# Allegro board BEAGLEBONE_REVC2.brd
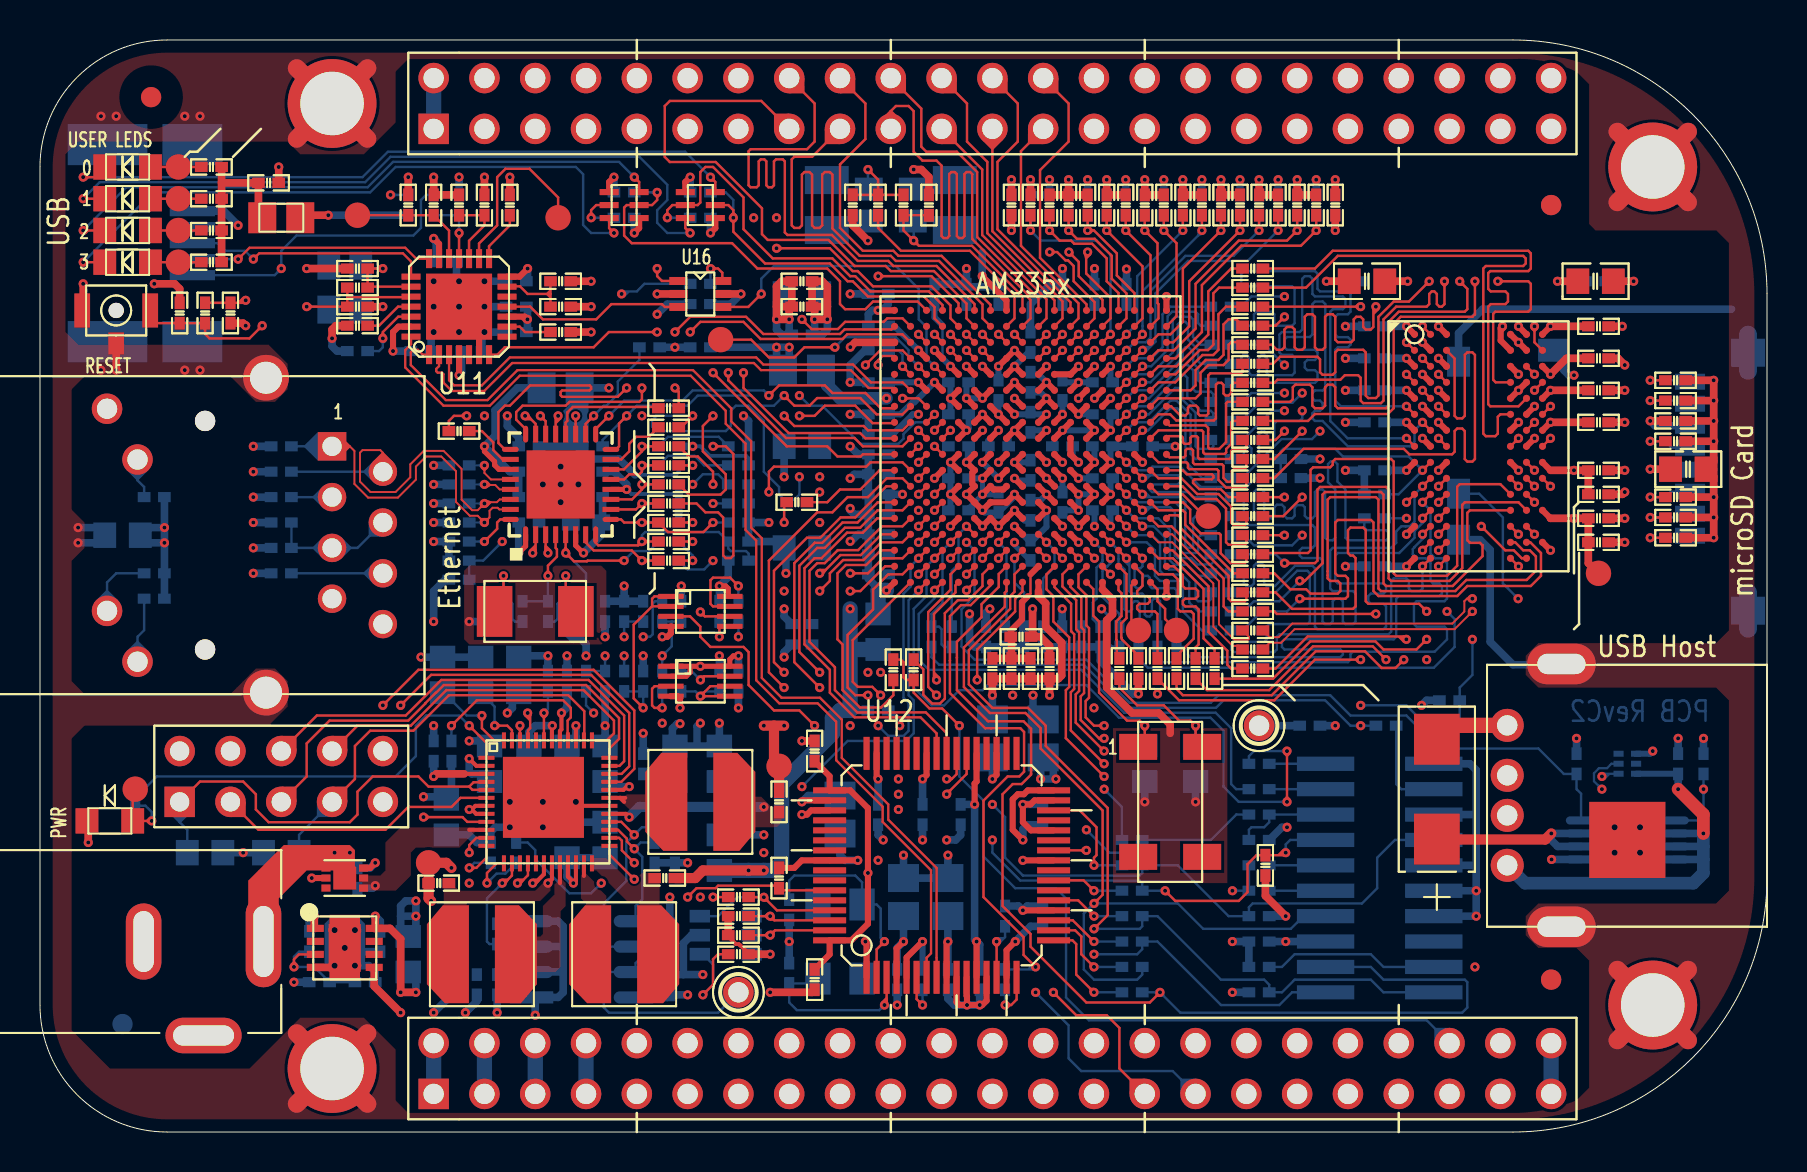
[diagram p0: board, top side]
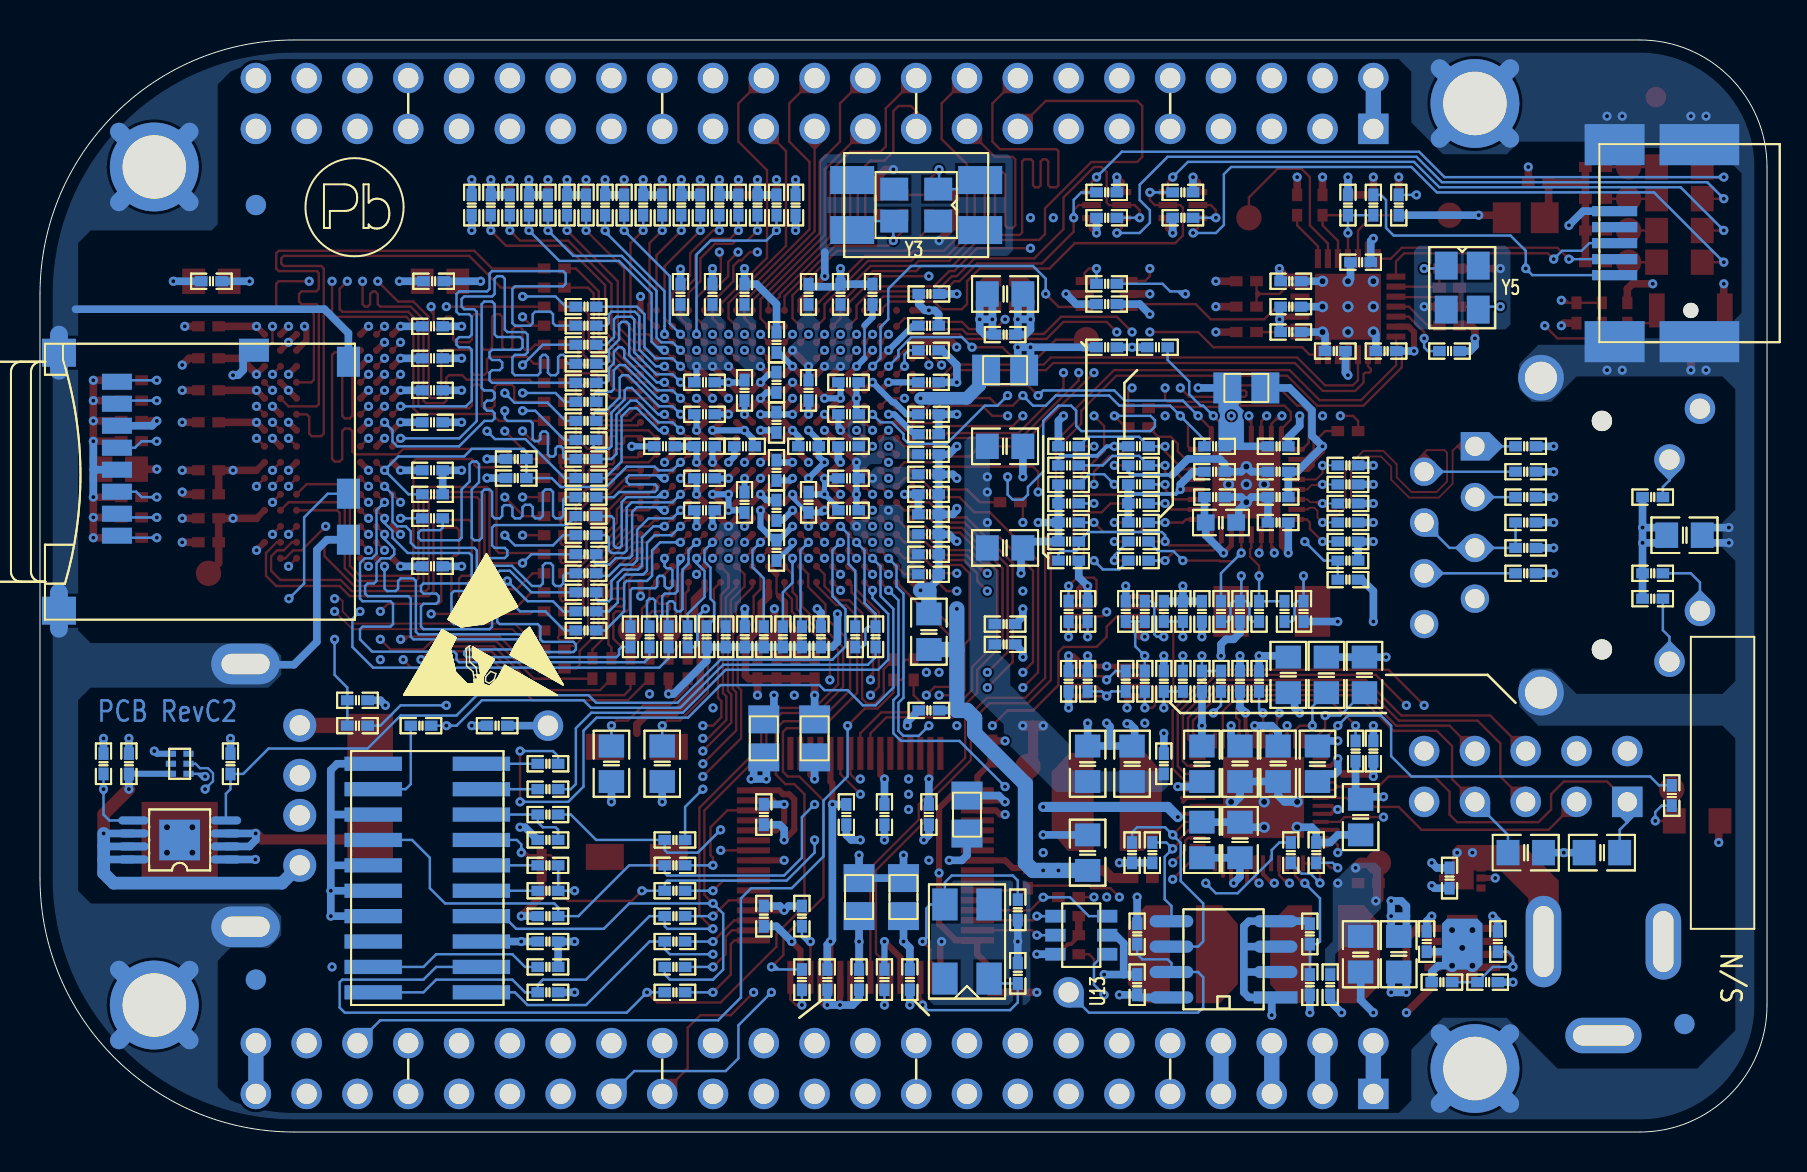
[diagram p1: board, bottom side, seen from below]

Outline 86.36 x 54.61 mm; copper layers: TOP, LYR2_GND, LYR3, LYR4, LYR5_PWR, BOTTOM. Coordinates in mm from the lower left corner of the outline.
Outline path: 0,48.26 0,6.35 arc(1.86,1.86) 6.35,0 73.66,0 arc(82.64,3.72) 86.36,12.7 86.36,41.91 arc(82.64,50.89) 73.66,54.61 6.35,54.61 arc(1.86,52.75) 0,48.26

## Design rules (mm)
net group FT_D: nets FT_DM FT_DP
net group PDDR_CLK: nets PDDR_CLK PDDR_CLKN
net group RX: nets RXN RXP
net group TX: nets TXN TXP
net group USB0: nets USB0_DM USB0_DP
net group USB1: nets USB1_DM USB1_DP
net group USBD: nets USBDM_DN USBDP_UP
net group CLK: nets MMC0_CLKO
net group DDR_ADD: nets DDR_A0 DDR_A1 DDR_A2 DDR_A3 DDR_A4 DDR_A5 DDR_A6 DDR_A7 DDR_A8 DDR_A9 DDR_A10 DDR_A11 DDR_A12 DDR_A13 DDR_BA0 DDR_BA1 DDR_BA2 DDR_CASN DDR_CKE DDR_CLK DDR_CLKN DDR_CSN DDR_ODT DDR_RASN DDR_WEN
net group DDR_DATA: nets DDR_D0 DDR_D1 DDR_D2 DDR_D3 DDR_D4 DDR_D5 DDR_D6 DDR_D7 DDR_D8 DDR_D9 DDR_D10 DDR_D11 DDR_D12 DDR_D13 DDR_D14 DDR_D15 DDR_DQM0 DDR_DQM1 DDR_DQS0 DDR_DQS1 DDR_DQSN0 DDR_DQSN1

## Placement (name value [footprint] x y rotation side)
C1  4.7uF,6.3V  [402]  15.88 12.7 90 bottom
C2  4.7uF,6.3V  [402]  22.54 13.97 90 bottom
C3  10uF,10V  [805]  8.26 13.97 180 bottom
C4  10uF,10V  [805]  20.13 22.86 270 bottom
C5  10uF,10V  [805]  22.03 22.86 270 bottom
C6  4.7uF,6.3V  [402]  17.02 9.53 270 bottom
C7  4.7uF,50V  [805]  12.06 13.97 180 bottom
C8  10uF,10V  [805]  26.35 14.61 270 bottom
C9  10uF,10V  [805]  28.26 14.61 270 bottom
C10  10uF,10V  [805]  28.26 18.41 270 bottom
C14  10uF,10V  [805]  31.75 18.41 270 bottom
C15  10uF,10V  [805]  33.97 13.97 270 bottom
C16  22uF,6.3V  [805]  20.32 8.89 270 bottom
C17  10uF,10V  [805]  24.45 18.41 90 bottom
C18  10uF,10V  [805]  26.35 18.41 90 bottom
C19  10uF,10V  [805]  22.48 18.41 270 bottom
C20  2.2uF,6.3V  [402]  19.68 19.05 90 bottom
C21  0.01uf,16V,DNI  [402]  34.92 22.54 270 bottom
C22  0.01uf,16V,DNI  [402]  33.97 22.54 90 bottom
C23  25pF,50V  [805]  55.24 18.41 90 bottom
C24  25pF,50V  [805]  57.78 18.41 90 bottom
C25  0.01uf,16V  [402]  30.16 26.04 90 bottom
C26  18pF,50V  [402]  44.45 46.35 90 top
C27  18pF,50V  [402]  40.64 46.35 270 top
C28  0.01uf,16V  [402]  49.53 23.18 270 top
C29  0.01uf,16V  [402]  48.58 23.18 270 top
C30  0.001uf,50V  [402]  47.62 23.18 270 top
C31  10uF,10V  [805]  38.1 29.21 0 bottom
C32  10uF,10V  [805]  38.1 34.29 0 bottom
C33  0.01uf,16V  [402]  45.93 37.49 180 bottom
C34  0.01uf,16V  [402]  49.53 37.49 270 bottom
C35  0.01uf,16V  [402]  51.13 37.09 90 bottom
C36  0.01uf,16V  [402]  41.93 34.89 180 bottom
C37  0.01uf,16V  [402]  47.93 34.29 0 bottom
C38  0.01uf,16V  [402]  49.53 35.49 270 bottom
C39  0.01uf,16V  [402]  51.13 34.29 0 bottom
C40  0.01uf,16V  [402]  49.53 33.09 90 bottom
C41  0.01uf,16V  [402]  51.13 31.49 90 bottom
C42  0.01uf,16V  [402]  48.58 46.35 270 bottom
C43  0.01uf,16V  [402]  49.53 39.49 270 bottom
C44  10uF,10V  [805]  41.91 25.02 270 bottom
C45  0.01uf,16V  [402]  47.93 31.49 90 bottom
C46  0.01uf,16V  [402]  41.91 21.08 0 bottom
C47  0.01uf,16V  [402]  45.93 34.29 180 bottom
C48  0.01uf,16V  [402]  41.93 31.89 180 bottom
C49  0.01uf,16V  [402]  41.93 30.89 180 bottom
C50  10uF,10V  [805]  33.97 18.41 270 bottom
C51  0.01uf,16V  [402]  38.1 42.55 180 top
C52  0.01uf,16V  [402]  38.1 41.27 0 top
C53  0.01uf,16V  [402]  38.1 24.38 180 bottom
C54  0.01uf,16V  [402]  38.1 25.4 180 bottom
C55  0.01uf,16V  [402]  30.16 18.41 90 bottom
C56  0.01uf,16V  [402]  46.33 41.89 90 bottom
C57  0.01uf,16V  [402]  47.31 24.77 270 bottom
C58  0.01uf,16V  [402]  45.93 32.69 180 bottom
C59  0.01uf,16V  [402]  64.77 46.35 90 bottom
C60  0.01uf,16V  [402]  45.93 35.89 180 bottom
C61  0.01uf,16V  [402]  38.1 39.88 180 bottom
C62  0.01uf,16V  [402]  45.93 31.09 180 bottom
C63  0.01uf,16V  [402]  41.91 41.91 180 bottom
C64  0.01uf,16V  [402]  49.53 31.09 270 bottom
C65  0.01uf,16V  [402]  53.13 37.49 0 bottom
C66  0.01uf,16V  [402]  54.33 41.89 270 bottom
C67  0.01uf,16V  [402]  48.58 46.35 90 top
C68  0.01uf,16V  [402]  64.77 46.35 90 top
C69  10uF,10V  [805]  38.1 41.91 180 bottom
C70  0.01uf,16V  [402]  52.73 41.89 270 bottom
C71  0.01uf,16V  [402]  41.93 33.89 0 bottom
C72  0.01uf,16V  [402]  33.02 39.24 180 bottom
C73  0.01uf,16V  [402]  41.93 32.89 180 bottom
C74  0.01uf,16V  [402]  44.73 41.89 90 bottom
C75  0.01uf,16V  [402]  51.13 41.89 90 bottom
C76  0.01uf,16V  [402]  41.93 29.89 180 bottom
C77  0.01uf,16V  [402]  41.93 28.89 180 bottom
C78  0.01uf,16V  [402]  41.93 37.49 180 bottom
C79  0.01uf,16V  [402]  41.93 27.89 180 bottom
C80  0.01uf,16V  [402]  41.93 40.32 180 bottom
C81  0.01uf,16V  [402]  41.93 35.89 180 bottom
C82  0.01uf,16V  [402]  49.53 29.09 270 bottom
C83  1uF,10V  [402]  50.16 24.77 270 bottom
C84  1uF,10V  [402]  48.26 24.77 270 bottom
C85  1uF,10V  [402]  49.21 24.77 270 bottom
C86  0.01uf,16V  [402]  52.07 24.77 270 bottom
C87  0.01uf,16V  [402]  50.48 23.18 270 top
C88  0.01uf,16V  [402]  47.93 37.09 270 bottom
C89  10uF,10V  [805]  77.79 42.55 180 top
C90  0.01uf,16V  [402]  53.13 35.89 180 bottom
C91  0.01uf,16V  [402]  53.13 34.29 180 bottom
C92  0.01uf,16V  [402]  53.13 32.69 180 bottom
C93  0.01uf,16V  [402]  53.13 31.09 180 bottom
C94  0.01uf,16V  [402]  77.79 42.55 0 bottom
C95  0.01uf,16V  [402]  66.67 42.55 180 bottom
C96  0.01uf,16V  [402]  55.13 34.29 0 bottom
C97  1uF,10V  [402]  53.02 24.77 270 bottom
C98  0.01uf,16V  [402]  51.12 24.77 270 bottom
C99  0.01uf,16V  [402]  47.93 41.89 90 bottom
C100  4.7uF,6.3V  [402]  11.43 47.47 0 top
C101  1uF,10V,DNI  [402]  6.99 40.96 90 top
C102  0.1uf,16V  [402]  31.5 7.37 90 bottom
C103  0.01uf,16V  [402]  66.73 40.29 180 bottom
C104  0.01uf,16V  [402]  66.73 38.69 180 bottom
C105  0.01uf,16V  [402]  66.73 37.09 180 bottom
C106  0.01uf,16V  [402]  66.73 35.49 180 bottom
C107  0.01uf,16V  [402]  66.73 33.09 180 bottom
C108  0.01uf,16V  [402]  66.73 28.29 180 bottom
C109  0.01uf,16V  [402]  77.93 40.29 0 top
C110  0.01uf,16V  [402]  77.93 38.69 0 top
C111  0.01uf,16V  [402]  77.93 37.09 0 top
C112  0.01uf,16V  [402]  77.93 35.49 0 top
C113  0.01uf,16V  [402]  77.93 33.09 0 top
C114  0.01uf,16V  [402]  77.93 31.89 0 top
C115  0.01uf,16V  [402]  77.93 30.69 0 top
C116  22uF,6.3V  [805]  66.36 42.55 180 top
C117  0.01uf,16V  [402]  77.93 29.49 0 top
C118  0.01uf,16V  [402]  66.73 31.89 180 bottom
C119  0.1uf,16V  [402]  24.45 30.48 0 bottom
C120  0.1uf,16V  [402]  24.45 31.75 0 bottom
C121  4.7uF,6.3V  [402]  24.45 33.02 0 bottom
C122  0.1uf,16V  [402]  24.45 34.29 180 bottom
C123  0.1uf,16V  [402]  27.62 33.02 180 bottom
C124  470pF  [0603]  27.3 30.48 180 bottom
C125  1uF,10V  [402]  27.62 31.75 180 bottom
C126  15pF,DNI  [402]  12.06 34.29 180 bottom
C127  15pF,DNI  [402]  12.06 33.02 180 bottom
C128  15pF,DNI  [402]  12.06 31.75 180 bottom
C129  15pF,DNI  [402]  12.06 27.94 180 bottom
C130  0.022uF,10V  [402]  12.06 30.48 180 bottom
C131  30pF,50V  [402]  23.18 26.04 270 bottom
C132  30pF,50V  [402]  26.35 26.04 270 bottom
C133  100uF,6.3V  [6032]  69.85 17.14 90 top
C134  0.01uf,16V  [402]  81.92 18.41 90 bottom
C135  10uF,10V  [805]  23.94 22.86 90 bottom
C136  0.1uf,16V  [402]  20.95 46.35 90 top
C137  18pF,50V  [402]  15.88 41.27 180 top
C138  0.1uf,16V  [402]  23.81 42.55 180 bottom
C139  4.7uF,6.3V  [402]  23.81 40.01 180 bottom
C140  0.1uf,16V  [402]  23.81 41.27 180 bottom
C141  0.1uf,16V  [402]  21.59 39.05 0 bottom
C142  0.1uf,16V  [402]  20.32 43.5 0 bottom
C143  0.1uf,16V  [402]  19.05 39.05 0 bottom
C144  18pF,50V  [402]  15.88 43.18 0 top
C145  0.1uf,16V,DNI  [402]  15.88 40.32 180 top
C146  0.1uf,16V,DNI  [402]  26.04 40.01 0 top
C147  0.1uf,16V  [402]  50.16 15.88 270 bottom
C148  0.1uf,16V  [402]  44.13 15.88 270 bottom
C149  0.1uf,16V  [402]  33.02 41.4 0 bottom
C150  0.1uf,16V  [402]  41.91 15.88 90 bottom
C151  0.1uf,16V  [402]  50.16 10.79 270 bottom
C152  4.7uF,6.3V  [402]  46.04 15.88 270 bottom
C153  27pF,50V  [402]  37.47 11.11 90 bottom
C154  0.01uf,16V  [402]  60.96 9.53 180 bottom
C155  27pF,50V  [402]  37.47 7.94 270 bottom
C156  0.1uf,16V  [402]  60.96 14.61 0 bottom
C157  0.1uf,16V  [402]  28.26 26.04 270 bottom
C158  0.1uf,16V  [402]  42.86 7.62 270 bottom
C159  10uF,10V  [805]  82.42 33.15 180 top
C160  0.1uf,16V  [402]  81.79 35.56 180 top
C161  0.1uf,16V  [402]  45.4 7.62 270 bottom
C162  0.1uf,16V  [402]  38.73 19.05 270 top
C163  0.1uf,16V  [402]  38.73 7.62 90 top
C164  0.1uf,16V  [402]  46.99 7.62 90 bottom
C165  10uF,10V  [805]  20.32 15.75 90 bottom
C166  0.1uf,16V  [402]  13.46 9.53 90 bottom
D1  598-8170-107F  [LED0805-1]  3.49 15.56 0 top
D2  598-8170-107F  [LED0805-1]  4.38 48.26 0 top
D3  598-8170-107F  [LED0805-1]  4.38 46.67 0 top
D4  598-8170-107F  [LED0805-1]  4.38 45.09 0 top
D5  598-8170-107F  [LED0805-1]  4.38 43.5 0 top
FB1  150OHM800mA  [SM-7351-IND-0805]  38.1 38.1 0 bottom
FB2  150OHM800mA  [SM-7351-IND-0805]  50.16 19.68 270 bottom
FB3  150OHM800mA  [SM-7351-IND-0805]  47.62 19.68 270 bottom
FB4  150OHM800mA  [SM-7351-IND-0805]  12.06 45.72 0 top
FB5  150OHM800mA  [SM-7351-IND-0805]  26.04 37.21 180 bottom
FB6  150OHM800mA  [SM-7351-IND-0805]  45.4 11.75 270 bottom
FB7  150OHM800mA  [SM-7351-IND-0805]  43.18 11.75 270 bottom
FB8  150OHM800mA  [SM-7351-IND-0805]  40.01 15.88 90 bottom
L1  2.2uH,2.6A  [VLCF5020T]  22.1 8.89 180 top
L2  2.2uH,2.6A  [VLCF5020T]  29.21 8.89 0 top
L3  2.2uH,2.6A  [VLCF5020T]  33.02 16.51 0 top
MTG1  MHOLE  [MTGH200C125D_PL]  14.61 3.17 90 top
MTG2  MHOLE  [MTGH200C125D_PL]  80.64 6.35 90 top
MTG3  MHOLE  [MTGH200C125D_PL]  14.61 51.44 90 top
MTG4  MHOLE  [MTGH200C125D_PL]  80.64 48.26 90 top
NOREF  -  [unnamed]  5.56 51.75 270 top
NOREF#2  -  [#2]  0 0 0 top
NOREF#3  -  [#2]  85.72 39.05 0 top
NOREF#4  -  [#2]  85.72 28.57 0 top
NOREF#5  -  [#2]  6.35 54.61 0 top
NOREF#6  -  [#2]  -11.96 0 90 top
NOREF#7  -  [#2]  80.64 6.35 0 top
NOREF#8  -  [#2]  80.64 48.26 0 top
NOREF#9  -  [#2]  80.64 6.35 0 top
NOREF#10  -  [#2]  14.61 51.44 0 top
NOREF#11  -  [unnamed]  75.56 46.35 270 top
NOREF#12  -  [#2]  14.61 3.17 0 top
NOREF#13  -  [#2]  86.36 12.7 0 top
NOREF#14  -  [#2]  14.61 3.17 0 top
NOREF#15  -  [#2]  81.92 52.07 0 top
NOREF#16  -  [unnamed]  75.56 7.62 270 top
NOREF#17  -  [#2]  0 -11.96 0 top
NOREF#18  -  [#2]  -368.3 -256.54 0 top
NOREF#19  -  [#2]  86.36 39.69 0 top
NOREF#20  -  [#2]  85.72 28.57 0 top
NOREF#21  -  [#2]  0 0 0 top
NOREF#22  -  [#2]  -368.17 -256.47 0 top
NOREF#23  -  [#2]  86.36 27.94 0 top
NOREF#24  -  [#2]  1.91 53.34 180 bottom
NOREF#25  -  [unnamed]  75.56 7.62 270 bottom
NOREF#26  -  [unnamed]  4.13 5.4 270 bottom
NOREF#27  -  [unnamed]  75.56 46.35 270 bottom
P2  USB-A Conn. - 87520-xx1xx  [USB_A_SH]  73.37 13.34 90 top
P3  mini USB-B  [USB-MINI-SMT-NUM]  7.62 44.45 90 bottom
P4  MOLEX 502570-001  [CON8SMD-MICRO_SD_14P3X15P9]  70.61 33.02 90 bottom
P5  PJ-200A  [CONN3-PWR-PJ102A]  11.18 9.53 180 top
P6  HDR5x2  [HEADER10X2]  6.99 16.51 90 top
P7  CTI JTAG,DNI  [HEADER10X2_SMD]  66.99 12.7 90 bottom
P8  FEMALE HEADER 2x23  [HEADER23X2]  19.68 50.16 0 top
P9  FEMALE HEADER 2x23  [HEADER23X2]  19.68 1.91 0 top
P10  WE_7499010211A  [RJ45-7499010211A]  14.61 34.29 270 top
Q1  DMC56404  [SMINI6-F3-B]  33.02 46.35 90 top
Q2  DMC56404  [SMINI6-F3-B]  29.21 46.35 90 top
R1  4.75K,1%  [402]  22.86 9.91 270 bottom
R2  12.1K,1%  [402]  22.86 7.37 270 bottom
R3  .1,0805  [805]  18.41 8.89 90 bottom
R4  1.5K,5%  [402]  30.73 13.97 90 bottom
R5  10K,1%,DNI  [402]  34.92 31.43 0 bottom
R6  470,5%  [402]  4.76 16.83 270 bottom
R7  1.5K,5%  [402]  31.75 13.97 90 bottom
R8  100K,1%  [402]  27.3 22.54 270 bottom
R9  100K,1%  [402]  28.26 22.54 90 bottom
R10  0,DNI  [402]  29.21 22.54 90 bottom
R11  0,1%  [402]  23.81 13.97 90 bottom
R12  0,1%  [402]  19.94 12.45 180 top
R13  0,1%  [402]  36.96 16.51 90 top
R14  0,1%  [402]  21.84 7.37 270 bottom
R15  0,1%  [402]  26.35 22.54 90 bottom
R16  470,5%  [402]  5.71 27.94 180 bottom
R17  1.1K,1%,DNI  [402]  32.07 22.54 270 bottom
R18  12.1K,1%  [402]  32.07 26.04 90 bottom
R19  0,1%  [402]  20.57 19.05 270 bottom
R20  100K,1%  [402]  29.21 26.04 90 bottom
R21  1M,1%  [402]  43.18 46.35 90 top
R22  0,1%  [402]  53.98 23.18 90 top
R23  10K,1%  [402]  9.53 40.96 90 top
R24  0,1%  [402]  41.91 46.35 270 top
R25  33,0402  [402]  60.64 31.75 180 top
R26  33,0402  [402]  56.83 24.77 90 bottom
R27  0,1%  [402]  8.26 40.96 270 top
R28  0,1%  [402]  34.92 26.04 270 bottom
R29  33,0402  [402]  59.05 28.89 180 bottom
R30  33,0402  [402]  59.05 26.04 180 bottom
R31  33,0402  [402]  58.74 23.18 90 top
R32  33,0402  [402]  57.78 23.18 90 top
R33  33,0402  [402]  54.93 24.77 90 bottom
R34  33,0402  [402]  60.64 26.04 180 top
R35  33,0402  [402]  59.05 25.08 180 bottom
R36  33,0402  [402]  60.64 23.18 180 top
R37  33,0402  [402]  59.05 27.94 180 bottom
R38  33,0402  [402]  60.64 27.94 180 top
R39  33,0402  [402]  59.05 26.99 180 bottom
R40  33,0402  [402]  59.05 31.75 180 bottom
R41  33,0402  [402]  55.88 24.77 90 bottom
R42  33,0402  [402]  60.64 26.99 180 top
R43  33,0402  [402]  55.88 23.18 90 top
R44  33,0402  [402]  59.05 36.51 180 bottom
R45  33,0402  [402]  59.05 37.47 180 bottom
R46  33,0402  [402]  60.64 40.32 180 top
R47  33,0402  [402]  60.64 41.27 180 top
R48  33,0402  [402]  59.05 38.42 180 bottom
R49  33,0402  [402]  59.05 39.37 180 bottom
R50  33,0402  [402]  59.05 40.32 180 bottom
R51  33,0402  [402]  59.05 41.27 180 bottom
R52  33,0402  [402]  60.64 33.66 180 top
R53  33,0402  [402]  60.64 34.61 180 top
R54  33,0402  [402]  60.64 35.56 180 top
R55  33,0402  [402]  59.05 32.7 180 bottom
R56  33,0402  [402]  59.05 33.66 180 bottom
R57  33,0402  [402]  59.05 34.61 180 bottom
R58  33,0402  [402]  59.05 35.56 180 bottom
R59  33,0402  [402]  60.64 38.42 180 top
R60  33,0402  [402]  60.64 24.13 180 top
R61  33,0402  [402]  60.64 25.08 180 top
R62  33,0402  [402]  59.05 30.8 180 bottom
R63  33,0402  [402]  60.64 30.8 180 top
R64  33,0402  [402]  60.64 28.89 180 top
R65  33,0402  [402]  59.05 29.84 180 bottom
R66  33,0402  [402]  56.83 23.18 90 top
R67  33,0402  [402]  60.64 39.37 180 top
R68  33,0402  [402]  60.64 42.23 180 top
R69  33,0402  [402]  60.64 43.18 180 top
R70  33,0402  [402]  60.64 32.7 180 top
R71  33,0402  [402]  60.64 36.51 180 top
R72  33,0402  [402]  60.64 37.47 180 top
R73  33,0402  [402]  60.64 29.84 180 top
R74  2.2K,1%  [402]  62.55 32.7 180 bottom
R75  2.2K,1%  [402]  62.55 33.66 0 bottom
R76  49.9,1%  [402]  63.5 20.32 0 bottom
R77  4.75K,1%  [402]  53.98 24.77 90 bottom
R78  0,1%  [402]  49.05 24.77 180 top
R79  10K,1%  [402]  54.93 23.18 90 top
R80  100K,1%  [402]  63.82 46.35 270 top
R81  100K,1%  [402]  62.87 46.35 270 top
R82  100K,1%  [402]  61.91 46.35 270 top
R83  100K,1%,DNI  [402]  60.96 46.35 270 top
R84  100K,1%  [402]  60.01 46.35 270 top
R85  100K,1%,DNI  [402]  59.05 46.35 270 top
R86  100K,1%,DNI  [402]  58.1 46.35 270 top
R87  100K,1%,DNI  [402]  57.15 46.35 270 top
R88  100K,1%,DNI  [402]  56.2 46.35 270 top
R89  100K,1%,DNI  [402]  55.24 46.35 270 top
R90  100K,1%,DNI  [402]  53.34 46.35 270 top
R91  100K,1%,DNI  [402]  51.44 46.35 270 top
R92  100K,1%,DNI  [402]  54.29 46.35 270 top
R93  100K,1%,DNI  [402]  52.39 46.35 270 top
R94  100K,1%  [402]  50.48 46.35 270 top
R95  100K,1%,DNI  [402]  49.53 46.35 270 top
R96  470,5%  [402]  8.57 48.26 180 top
R97  470,5%  [402]  8.57 46.67 180 top
R98  470,5%  [402]  8.57 45.09 180 top
R99  470,5%  [402]  8.57 43.5 180 top
R100  42.2K,1%,DNI  [402]  63.82 46.35 90 bottom
R101  42.2K,1%,DNI  [402]  62.87 46.35 90 bottom
R102  42.2K,1%,DNI  [402]  61.91 46.35 90 bottom
R103  42.2K,1%  [402]  60.96 46.35 90 bottom
R104  42.2K,1%,DNI  [402]  60.01 46.35 90 bottom
R105  42.2K,1%  [402]  59.05 46.35 90 bottom
R106  42.2K,1%  [402]  58.1 46.35 90 bottom
R107  42.2K,1%  [402]  57.15 46.35 90 bottom
R108  42.2K,1%  [402]  56.2 46.35 90 bottom
R109  42.2K,1%  [402]  55.24 46.35 90 bottom
R110  42.2K,1%  [402]  53.34 46.35 90 bottom
R111  42.2K,1%  [402]  51.44 46.35 90 bottom
R112  42.2K,1%  [402]  54.29 46.35 90 bottom
R113  42.2K,1%  [402]  52.39 46.35 90 bottom
R114  42.2K,1%,DNI  [402]  50.48 46.35 90 bottom
R115  42.2K,1%  [402]  49.53 46.35 90 bottom
R116  100K,1%  [402]  33.02 45.72 0 bottom
R117  100K,1%  [402]  33.02 46.99 180 bottom
R118  100K,1%  [402]  29.21 45.72 0 bottom
R119  100K,1%  [402]  29.21 46.99 180 bottom
R120  0,1%  [402]  66.73 30.69 0 bottom
R121  0,1%  [402]  25.4 22.54 90 bottom
R122  10K,1%  [402]  31.43 34.29 0 bottom
R123  10K,1%  [402]  31.43 31.43 0 bottom
R124  10K,1%  [402]  31.43 32.38 0 bottom
R125  10K,1%  [402]  31.43 33.34 0 bottom
R126  10K,1%,DNI  [402]  34.92 33.34 180 bottom
R127  10K,1%,DNI  [402]  34.92 34.29 0 bottom
R128  470,5%  [402]  5.71 31.75 180 bottom
R129  49.9,1%  [402]  20.95 30.48 180 bottom
R130  49.9,1%  [402]  20.95 31.43 180 bottom
R131  1.5K,5%  [402]  27.62 34.29 0 bottom
R132  100,1%  [402]  31.43 31.43 180 top
R133  49.9,1%  [402]  20.95 32.38 180 bottom
R134  49.9,1%  [402]  20.95 33.34 180 bottom
R135  100,1%  [402]  31.43 32.38 180 top
R136  100,1%  [402]  31.43 28.57 180 bottom
R137  100,1%  [402]  31.43 33.34 180 top
R138  .1,0805  [805]  4.13 29.84 180 bottom
R139  100,1%  [402]  31.43 34.29 180 top
R140  1M,1%,DNI  [402]  25.4 26.04 270 bottom
R141  10K,1%  [402]  31.11 26.04 90 bottom
R142  0,1%  [402]  12.06 29.21 180 bottom
R143  0,1%,DNI  [402]  31.11 22.54 90 bottom
R144  10,1%  [402]  24.13 26.04 270 bottom
R145  12.1K,1%  [402]  20.95 29.53 180 bottom
R146  0,1%  [402]  41.93 39.09 180 bottom
R147  10K,1%  [402]  76.83 18.41 90 bottom
R148  10K,1%  [402]  83.19 18.41 270 bottom
R149  100K,1%  [402]  19.68 46.35 270 bottom
R150  52.3K,1%  [402]  13.97 7.49 180 bottom
R151  100K,1%  [402]  20.95 46.35 90 bottom
R152  4.75K,1%  [402]  18.41 46.35 90 bottom
R153  100,1%  [402]  31.43 30.48 180 top
R154  10K,1%,DNI  [402]  26.04 41.27 180 top
R155  10K,1%,DNI  [402]  18.41 46.35 270 top
R156  100K,1%  [402]  22.23 46.35 270 top
R157  12.1K,1%  [402]  15.88 39.05 180 bottom
R158  10K,1%  [402]  26.04 42.55 0 top
R159  100K,1%  [402]  19.68 46.35 90 top
R160  1M,1%,DNI  [402]  15.88 42.23 0 top
R161  0,1%  [402]  23.5 46.35 270 top
R162  4.75K,1%  [402]  33.97 26.04 270 bottom
R163  0,1%  [402]  33.02 42.42 180 bottom
R164  0,1%  [402]  48.26 7.62 90 bottom
R165  0,1%  [402]  54.61 6.99 0 bottom
R166  0,1%  [402]  54.61 8.26 0 bottom
R167  12.1K,1%  [402]  44.13 7.62 270 bottom
R168  0,1%  [402]  54.61 9.53 0 bottom
R169  0,1%  [402]  54.61 10.79 0 bottom
R170  0,1%  [402]  54.61 12.06 0 bottom
R171  0,1%  [402]  54.61 13.34 0 bottom
R172  0,1%  [402]  54.61 14.61 0 bottom
R173  10K,1%  [402]  34.92 9.84 0 top
R174  10K,1%  [402]  34.92 10.79 0 top
R175  2.2K,1%  [402]  48.26 10.79 270 bottom
R176  4.75K,1%  [402]  61.28 13.34 90 top
R177  0,DNI  [402]  60.96 8.26 180 bottom
R178  0,DNI  [402]  60.96 12.06 0 bottom
R179  4.75K,1%  [402]  60.96 10.79 180 bottom
R180  0,DNI  [402]  60.96 13.34 0 bottom
R181  10K,1%,DNI  [402]  36.96 12.7 270 top
R182  100,1%,DNI  [402]  60.96 15.88 0 bottom
R183  0,DNI  [402]  60.96 17.14 0 bottom
R184  0,DNI  [402]  67.31 20.32 180 bottom
R185  0,DNI  [402]  60.96 18.41 0 bottom
R186  4.75K,1%  [402]  60.96 6.99 180 bottom
R187  10K,1%  [402]  34.92 8.89 180 top
R188  2.2K,1%  [402]  34.92 11.75 0 top
R189  30.1K,1%  [402]  16.26 7.49 0 bottom
R190  10K,1%  [402]  81.79 29.72 180 top
R191  10K,1%  [402]  81.79 31.75 180 top
R192  10K,1%  [402]  81.79 34.54 180 top
R193  10K,1%  [402]  81.79 36.58 180 top
R194  10K,1%  [402]  81.79 37.59 180 top
R195  10K,1%  [402]  81.79 30.73 180 top
R196  10K,1%  [402]  70.48 21.59 180 bottom
R197  0,1%  [402]  70.48 20.32 180 bottom
R198  10K,1%,DNI  [402]  34.92 32.38 0 bottom
R199  0,1%  [402]  27.3 26.04 90 bottom
R200  0,1%,DNI  [402]  31.43 29.53 180 bottom
R201  33,0402  [402]  37.85 31.5 180 top
R202  0,1%  [402]  43.69 23.11 90 top
R203  100K,1%  [402]  30.16 22.54 270 bottom
R204  0,1%  [402]  31.24 12.7 0 top
R205  100,1%  [402]  31.43 29.53 180 top
R206  100,1%  [402]  31.43 36.2 180 top
R207  100,1%  [402]  31.43 35.24 180 top
R208  100,1%  [402]  20.95 35.05 0 top
R209  10,1%,DNI  [402]  31.43 28.57 180 top
R210  10K,1%  [402]  31.5 9.91 270 bottom
R211  10K,1%,DNI  [402]  31.43 30.48 0 bottom
R212  10K,1%  [402]  34.92 30.48 0 bottom
R213  10K,1%,DNI  [402]  34.92 28.57 180 bottom
R214  10K,1%  [402]  34.92 29.53 0 bottom
R215  10K,1%,DNI  [402]  20.95 27.62 180 bottom
R216  10K,1%  [402]  20.95 28.57 180 bottom
R217  0,1%  [402]  42.67 23.11 270 top
R218  0,1%  [402]  44.58 24.77 270 bottom
R219  10K,1%  [402]  5.71 26.67 0 bottom
R220  10K,1%  [402]  30.48 39.24 0 bottom
R221  0,1%  [402]  45.59 24.77 90 bottom
S1  B3U-1100  [SW3_4X2P5]  3.81 41.08 0 top
TP1  TESTPT1  [TP1-8040]  60.96 20.32 0 top
TP2  TESTPT1  [TP1-8040]  34.92 6.99 0 top
TP3  TESTPT1  [TP60C_SMD]  58.42 30.8 0 top
TP4  TESTPT1  [TP60C_SMD]  34.04 39.62 0 top
TP5  TESTPT1  [TP60C_SMD]  56.83 25.08 0 top
TP6  TESTPT1  [TP60C_SMD]  54.93 25.08 0 top
TP7  TESTPT1  [TP60C_SMD]  15.88 45.85 0 top
TP8  TESTPT1  [TP60C_SMD]  25.91 45.72 0 top
TP10  TESTPT1  [TP60C_SMD]  6.92 48.26 0 top
TP11  TESTPT1  [TP60C_SMD]  6.92 46.67 0 top
TP12  TESTPT1  [TP60C_SMD]  6.92 45.09 0 top
TP13  TESTPT1  [TP60C_SMD]  6.92 43.5 0 top
TP14  TESTPT1  [TP60C_SMD]  4.76 17.14 0 top
TP15  TESTPT1  [TP60C_SMD]  19.43 13.46 0 top
TP17  TESTPT1  [TP60C_SMD]  36.96 18.29 0 top
TP18  TESTPT1  [TP60C_SMD]  77.93 27.94 0 top
U1  NCP349  [DFN6-1P6X2]  15.24 12.7 270 top
U2  TPS65217b  [U_48_RSL]  25.4 16.51 0 top
U5  AM335X_ZCZ  [AM33XX_15X15]  49.53 34.29 180 top
U6  MT47H128M16RT-25E:C  [BGA84_8X12P5_P8MM]  71.93 34.29 0 top
U7  CAT24C256W  [SOIC_8]  27.18 8.64 90 bottom
U8  TPS73701DRBR  [DRB8-14X33-PAD]  15.24 9.21 270 top
U9  TPS2051 (DGN)  [DGN-16X60]  79.38 14.61 90 bottom
U10  TPD4S012  [U_6_DRY]  79.38 18.41 90 bottom
U11  USB2412_QFN28_MKTG  [QFN28_5X5]  20.95 41.27 90 top
U12  FT2232LQFN64  [LQFP64_10X10]  45.09 13.34 90 top
U13  93LC56B_SOT23-6  [SOT23-6]  34.29 9.84 90 bottom
U14  SN74LVC2G00DCU  [U_8_DCU]  33.02 26.04 270 top
U15  LAN8710A  [QFN32_5X5MM_EP3P3MM]  26.04 32.38 0 top
U16  SN74LVC2G07DCK  [DCK6_2P15X1P4]  33.02 41.91 270 top
U17  SN74AUP2G08,DNI  [U_8_DCU]  33.02 22.54 270 top
Y1  32.768KHz MC-306  [MC-306]  56.52 16.51 270 top
Y2  24MHz,DNI  [SM_CRY_SCC18]  42.55 46.35 270 bottom
Y3  24MHz  [XTAL4_3P2X2P5_SMD]  42.55 46.35 0 bottom
Y4  25.000MHz  [XTAL2_5X3P2_SMD]  24.77 26.04 180 top
Y5  24MHz  [XTAL4_3P2X2P5_SMD]  15.24 42.23 270 bottom
Y6  12.000MHz  [XTAL4_3P2X5SMD]  40.01 9.53 90 bottom

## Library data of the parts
C1 C2 C6 C100 C121 C139 C152 = CAP_4.7uF_X5R_6.3V_10%_0603
C3-C5 C8-C10 C14 C15 C17-C19 C31 C32 C44 C50 C69 C89 C135 C159 C165 = CAP_10uF_Y5V_10V_10%_0805
C7 = CAP_4.7uF_X5R_50V_10%_0805
C16 C116 = CAP_22uF_X5R_6.3V_120%_0805
C20 = CAP_2.2uF_X5R_6.3V_10%_0402
C21 C22 C25 C28 C29 C33-C43 C45-C49 C51-C68 C70-C82 C86-C88 C90-C96 C98 C99 C103-C115 C117 C118 C134 C154 = CAP_0.01uf_X7R_16V_10%_0402
C23 C24 = CAP_25PF_NPO_100V_5%_0805
C26 C27 C137 C144 C153 C155 = CAP_18PF_COG_50V_5%_0402
C30 = CAP_0.001_X7R_50V_5%_0402
C83-C85 C97 C101 C125 = CAP_1.0UF_X5R_10V_10%_0402
C102 C119 C120 C122 C123 C136 C138 C140-C143 C145-C151 C156-C158 C160-C164 C166 = CAP_0.1uF_X7R_16V_10% 0402
C124 = 470pF/5%/50V/C0G/0603_0
C126-C129 = CAP_0402_100pF_COG_50V
C130 = CAP_0402_0.1uf_X5R_10V
C131 C132 = CAP_30PF_COG_50V_5%_0402
C133 = CAP_100UF_TANT_6.3V_3528-21: Tolerance: TOL*; User Part Number: P/N*
D1-D5 = LED_LTST-C150GKT: User Part Number: X; Tolerance: X
FB1-FB8 = FER_180_200_0
L1-L3 = IND_2.2uH_2.6A_10%_SMD
MTG1-MTG4 = MHOLE
P2 = CONN_54819-0578_2: User Part Number: PART#; Tolerance: TOL
P3 = MINI-USB-AB-SOCKET
P4 = microSD_CONN_2
P5 = Power_Jack: Tolerance: X; User Part Number: X
P6 = HDR_10_F_2_0.1
P7 = HDR_10x2_CJTAG
P8 P9 = HDR_46_F_2_0.1_0.1
P10 = CONN_RJ45_MAG_WE_0
Q1 Q2 = RN1907
R1 R2 R23 R79 R142 R144 R147 R148 R154 R155 R158 R173 R174 R181 R187 R190-R196 R219 R220 = RES_10K_1/16W_1%_0402
R3 R138 = RES_0.1_0805
R4 R7 R131 = RES_1.5K_1/16W_5%_0402
R5 R10 R12 R19 R77 R121-R127 R162 R176 R179 R186 R198 R202 R211-R217 = RES_4.75K_1/16W_1%_0402
R6 R16 R96-R99 R128 = RES_470_1/10W_5%_0402
R8 R9 R80-R95 R100-R119 R141 R143 R146 R149 R151 R152 R156 R159 R203 = RES_100K_1/16W_1%_0402
R11 R14 R15 = RES_0_1/16W_1%_0402: signal model: 33OHMRESISTOR1_16W5_0402_SM_735_33
R13 = RES_4.75K_1/16W_1%_0402: signal model: 33OHMRESISTOR1_16W5_0402_SM_735_33
R17 = RES_1.1K_1/16W_1%_0402: signal model: 33OHMRESISTOR1_16W5_0402_SM_735_33
R18 R20 = RES_100K_1/16W_1%_0402: signal model: 33OHMRESISTOR1_16W5_0402_SM_735_33
R21 = RES_1M_1/16W_1%_0402: signal model: 33OHMRESISTOR1_16W5_0402_SM_735_33
R22 R24 R27 R28 R78 R161 R163-R166 R168-R172 R177 R178 R180 R183-R185 R197 R199 R200 R204 R210 R218 R221 = RES_0_1/16W_1%_0402
R25 R26 R29 R30 R32 R45 R46 R48 R50-R73 R201 = RES_33_0402
R31 R33-R44 R47 R49 = RES_33_0402: signal model: 33OHMRESISTOR1_16W5_0402_SM_735_33
R74 R75 R175 R188 = RES_2.2K_1/16W_1%_0402
R76 R129 R130 R133 R134 = RES_4.7K_0402
R120 = ZeroOhmResistor1/16W0402
R132 R135-R137 R139 R182 = RES_100_1/10W_5%_0402
R140 R160 = RES_1M_1/16W_1%_0402
R145 R157 R167 = RES_12.1K_1/16W_1%_0402
R150 R189 = RES_0: tolerance: 1%
R153 R205-R209 = 100-1/10W-1%-0603_4
S1 = SW_DP_MOM
TP1-TP8 TP10-TP15 TP17 TP18 = TESTPT1
U1 = PWR_NCP349_6-DFN: Tolerance: X; User Part Number: X
U2 = PWR_TPS65217_2
U5 = IC_AM335X_ZCE_1
U6 = MEM_MT47H64M16_FBGA84_1
U7 = CAT24C256W
U8 = TPS73701_0: Tolerance: X; User Part Number: X
U9 = TPS2061_0: User Part Number: X; Tolerance: X
U10 = PROT_TPD4S012
U11 = USB2412_QFN28_MKTG_2
U12 = IC_FT2232H_LQFP64
U13 = IC_93C46B_SSOT23-6
U14 = IC_SN74LVC2G38_8-VSSOP
U15 = LAN8710 QFN32_1
U16 = IC_SN74LVC2G07DCK
U17 = IC_SN74AUP2G08_8-VSSOP
Y1 = CRYS_32_768KHz_SMD32
Y2 Y3 Y5 = CRYS_24MHz_SCC
Y4 = Suntsu ITEMP 25MHz _0.005% 20pf
Y6 = XTAL_12MHZ_HC-49SMT_0: Tolerance: TOL*; User Part Number: P/N*

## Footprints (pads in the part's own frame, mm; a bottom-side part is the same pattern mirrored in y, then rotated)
402
  rect 0.635x0.508 smd: 1(-0.508,0) 2(0.508,0)
0603
  rect 0.889x0.813 smd: 1(-0.762,0) 2(0.762,0)
805
  rect 1.143x1.27 smd: 1(-0.889,0) 2(0.889,0)
6032
  rect 2.54x2.286 smd: 1(-2.499,0) 2(2.499,0)
AM33XX_15X15
  round 0.356 smd: A1(-6.8,6.8) A2(-6,6.8) A3(-5.2,6.8) A4(-4.4,6.8) A5(-3.6,6.8) A6(-2.8,6.8) A7(-2,6.8) A8(-1.2,6.8) A9(-0.4,6.8) A10(0.4,6.8) A11(1.2,6.8) A12(2,6.8) A13(2.8,6.8) A14(3.6,6.8) A15(4.4,6.8) A16(5.2,6.8) A17(6,6.8) A18(6.8,6.8) B1(-6.8,6) B2(-6,6) B3(-5.2,6) B4(-4.4,6) B5(-3.6,6) B6(-2.8,6) B7(-2,6) B8(-1.2,6) B9(-0.4,6) B10(0.4,6) B11(1.2,6) B12(2,6) B13(2.8,6) B14(3.6,6) B15(4.4,6) B16(5.2,6) B17(6,6) B18(6.8,6) C1(-6.8,5.2) C2(-6,5.2) C3(-5.2,5.2) C4(-4.4,5.2) C5(-3.6,5.2) C6(-2.8,5.2) C7(-2,5.2) C8(-1.2,5.2) C9(-0.4,5.2) C10(0.4,5.2) C11(1.2,5.2) C12(2,5.2) C13(2.8,5.2) C14(3.6,5.2) C15(4.4,5.2) C16(5.2,5.2) C17(6,5.2) C18(6.8,5.2) D1(-6.8,4.4) D2(-6,4.4) D3(-5.2,4.4) D4(-4.4,4.4) D5(-3.6,4.4) D6(-2.8,4.4) D7(-2,4.4) D8(-1.2,4.4) D9(-0.4,4.4) D10(0.4,4.4) D11(1.2,4.4) D12(2,4.4) D13(2.8,4.4) D14(3.6,4.4) D15(4.4,4.4) D16(5.2,4.4) D17(6,4.4) D18(6.8,4.4) E1(-6.8,3.6) E2(-6,3.6) E3(-5.2,3.6) E4(-4.4,3.6) E5(-3.6,3.6) E6(-2.8,3.6) E7(-2,3.6) E8(-1.2,3.6) E9(-0.4,3.6) E10(0.4,3.6) E11(1.2,3.6) E12(2,3.6) E13(2.8,3.6) E14(3.6,3.6) E15(4.4,3.6) E16(5.2,3.6) E17(6,3.6) E18(6.8,3.6) F1(-6.8,2.8) F2(-6,2.8) F3(-5.2,2.8) F4(-4.4,2.8) F5(-3.6,2.8) F6(-2.8,2.8) F7(-2,2.8) F8(-1.2,2.8) F9(-0.4,2.8) F10(0.4,2.8) F11(1.2,2.8) F12(2,2.8) F13(2.8,2.8) F14(3.6,2.8) F15(4.4,2.8) F16(5.2,2.8) F17(6,2.8) F18(6.8,2.8) G1(-6.8,2) G2(-6,2) G3(-5.2,2) G4(-4.4,2) G5(-3.6,2) G6(-2.8,2) G7(-2,2) G8(-1.2,2) G9(-0.4,2) G10(0.4,2) G11(1.2,2) G12(2,2) G13(2.8,2) G14(3.6,2) G15(4.4,2) G16(5.2,2) G17(6,2) G18(6.8,2) H1(-6.8,1.2) H2(-6,1.2) H3(-5.2,1.2) H4(-4.4,1.2) H5(-3.6,1.2) H6(-2.8,1.2) H7(-2,1.2) H8(-1.2,1.2) H9(-0.4,1.2) H10(0.4,1.2) H11(1.2,1.2) H12(2,1.2) H13(2.8,1.2) H14(3.6,1.2) H15(4.4,1.2) H16(5.2,1.2) H17(6,1.2) H18(6.8,1.2) J1(-6.8,0.4) J2(-6,0.4) J3(-5.2,0.4) J4(-4.4,0.4) J5(-3.6,0.4) J6(-2.8,0.4) J7(-2,0.4) J8(-1.2,0.4) J9(-0.4,0.4) J10(0.4,0.4) J11(1.2,0.4) J12(2,0.4) J13(2.8,0.4) J14(3.6,0.4) J15(4.4,0.4) J16(5.2,0.4) J17(6,0.4) J18(6.8,0.4) K1(-6.8,-0.4) K2(-6,-0.4) K3(-5.2,-0.4) K4(-4.4,-0.4) K5(-3.6,-0.4) K6(-2.8,-0.4) K7(-2,-0.4) K8(-1.2,-0.4) K9(-0.4,-0.4) K10(0.4,-0.4) K11(1.2,-0.4) K12(2,-0.4) K13(2.8,-0.4) K14(3.6,-0.4) K15(4.4,-0.4) K16(5.2,-0.4) K17(6,-0.4) K18(6.8,-0.4) L1(-6.8,-1.2) L2(-6,-1.2) L3(-5.2,-1.2) L4(-4.4,-1.2) L5(-3.6,-1.2) L6(-2.8,-1.2) L7(-2,-1.2) L8(-1.2,-1.2) L9(-0.4,-1.2) L10(0.4,-1.2) L11(1.2,-1.2) L12(2,-1.2) L13(2.8,-1.2) L14(3.6,-1.2) L15(4.4,-1.2) L16(5.2,-1.2) L17(6,-1.2) L18(6.8,-1.2) M1(-6.8,-2) M2(-6,-2) M3(-5.2,-2) M4(-4.4,-2) M5(-3.6,-2) M6(-2.8,-2) M7(-2,-2) M8(-1.2,-2) M9(-0.4,-2) M10(0.4,-2) M11(1.2,-2) M12(2,-2) M13(2.8,-2) M14(3.6,-2) M15(4.4,-2) M16(5.2,-2) M17(6,-2) M18(6.8,-2) N1(-6.8,-2.8) N2(-6,-2.8) N3(-5.2,-2.8) N4(-4.4,-2.8) N5(-3.6,-2.8) N6(-2.8,-2.8) N7(-2,-2.8) N8(-1.2,-2.8) N9(-0.4,-2.8) N10(0.4,-2.8) N11(1.2,-2.8) N12(2,-2.8) N13(2.8,-2.8) N14(3.6,-2.8) N15(4.4,-2.8) N16(5.2,-2.8) N17(6,-2.8) N18(6.8,-2.8) P1(-6.8,-3.6) P2(-6,-3.6) P3(-5.2,-3.6) P4(-4.4,-3.6) P5(-3.6,-3.6) P6(-2.8,-3.6) P7(-2,-3.6) P8(-1.2,-3.6) P9(-0.4,-3.6) P10(0.4,-3.6) P11(1.2,-3.6) P12(2,-3.6) P13(2.8,-3.6) P14(3.6,-3.6) P15(4.4,-3.6) P16(5.2,-3.6) P17(6,-3.6) P18(6.8,-3.6) R1(-6.8,-4.4) R2(-6,-4.4) R3(-5.2,-4.4) R4(-4.4,-4.4) R5(-3.6,-4.4) R6(-2.8,-4.4) R7(-2,-4.4) R8(-1.2,-4.4) R9(-0.4,-4.4) R10(0.4,-4.4) R11(1.2,-4.4) R12(2,-4.4) R13(2.8,-4.4) R14(3.6,-4.4) R15(4.4,-4.4) R16(5.2,-4.4) R17(6,-4.4) R18(6.8,-4.4) T1(-6.8,-5.2) T2(-6,-5.2) T3(-5.2,-5.2) T4(-4.4,-5.2) T5(-3.6,-5.2) T6(-2.8,-5.2) T7(-2,-5.2) T8(-1.2,-5.2) T9(-0.4,-5.2) T10(0.4,-5.2) T11(1.2,-5.2) T12(2,-5.2) T13(2.8,-5.2) T14(3.6,-5.2) T15(4.4,-5.2) T16(5.2,-5.2) T17(6,-5.2) T18(6.8,-5.2) U1(-6.8,-6) U2(-6,-6) U3(-5.2,-6) U4(-4.4,-6) U5(-3.6,-6) U6(-2.8,-6) U7(-2,-6) U8(-1.2,-6) U9(-0.4,-6) U10(0.4,-6) U11(1.2,-6) U12(2,-6) U13(2.8,-6) U14(3.6,-6) U15(4.4,-6) U16(5.2,-6) U17(6,-6) U18(6.8,-6) V1(-6.8,-6.8) V2(-6,-6.8) V3(-5.2,-6.8) V4(-4.4,-6.8) V5(-3.6,-6.8) V6(-2.8,-6.8) V7(-2,-6.8) V8(-1.2,-6.8) V9(-0.4,-6.8) V10(0.4,-6.8) V11(1.2,-6.8) V12(2,-6.8) V13(2.8,-6.8) V14(3.6,-6.8) V15(4.4,-6.8) V16(5.2,-6.8) V17(6,-6.8) V18(6.8,-6.8)
BGA84_8X12P5_P8MM
  round 0.356 smd: A1(-3.2,5.6) A2(-2.4,5.6) A3(-1.6,5.6) A7(1.6,5.6) A8(2.4,5.6) A9(3.2,5.6) B1(-3.2,4.8) B2(-2.4,4.8) B3(-1.6,4.8) B7(1.6,4.8) B8(2.4,4.8) B9(3.2,4.8) C1(-3.2,4) C2(-2.4,4) C3(-1.6,4) C7(1.6,4) C8(2.4,4) C9(3.2,4) D1(-3.2,3.2) D2(-2.4,3.2) D3(-1.6,3.2) D7(1.6,3.2) D8(2.4,3.2) D9(3.2,3.2) E1(-3.2,2.4) E2(-2.4,2.4) E3(-1.6,2.4) E7(1.6,2.4) E8(2.4,2.4) E9(3.2,2.4) F1(-3.2,1.6) F2(-2.4,1.6) F3(-1.6,1.6) F7(1.6,1.6) F8(2.4,1.6) F9(3.2,1.6) G1(-3.2,0.8) G2(-2.4,0.8) G3(-1.6,0.8) G7(1.6,0.8) G8(2.4,0.8) G9(3.2,0.8) H1(-3.2,0) H2(-2.4,0) H3(-1.6,0) H7(1.6,0) H8(2.4,0) H9(3.2,0) J1(-3.2,-0.8) J2(-2.4,-0.8) J3(-1.6,-0.8) J7(1.6,-0.8) J8(2.4,-0.8) J9(3.2,-0.8) K2(-2.4,-1.6) K3(-1.6,-1.6) K7(1.6,-1.6) K8(2.4,-1.6) K9(3.2,-1.6) L1(-3.2,-2.4) L2(-2.4,-2.4) L3(-1.6,-2.4) L7(1.6,-2.4) L8(2.4,-2.4) M2(-2.4,-3.2) M3(-1.6,-3.2) M7(1.6,-3.2) M8(2.4,-3.2) M9(3.2,-3.2) N1(-3.2,-4) N2(-2.4,-4) N3(-1.6,-4) N7(1.6,-4) N8(2.4,-4) P2(-2.4,-4.8) P3(-1.6,-4.8) P7(1.6,-4.8) P8(2.4,-4.8) P9(3.2,-4.8) R1(-3.2,-5.6) R2(-2.4,-5.6) R3(-1.6,-5.6) R7(1.6,-5.6) R8(2.4,-5.6)
CON8SMD-MICRO_SD_14P3X15P9
  rect 0.8x1.5 smd: 1(-3.2,11.9) 2(-2.1,11.9) 3(-1,11.9) 4(0.1,11.9) 5(1.2,11.9) 6(2.3,11.9) 7(3.4,11.9) 8(4.5,11.9)
  rect 1.15x1.5 smd: 9(6.075,5.05)
  rect 1.5x1.15 smd: 10(5.5,0.325) 11(-1.1,0.325) 12(-3.4,0.325)
  rect 1.4x1.7 smd: 13(-6.95,14.8) 14(5.95,14.8)
CONN3-PWR-PJ102A
  oval 1.778x4.572 hole 1.016x3.556: 1(0,0)
  oval 1.778x3.81 hole 1.016x3.048: 2(5.994,0)
  oval 3.81x1.778 hole 3.048x1.016: 3(2.997,4.699)
DCK6_2P15X1P4
  rect 0.4x0.9 smd: 1(-0.65,-1.1) 2(0,-1.1) 3(0.65,-1.1) 4(0.65,1.1) 5(0,1.1) 6(-0.65,1.1)
DFN6-1P6X2
  rect 0.356x0.457 smd: 1(-0.5,-0.94) 2(0,-0.94) 3(0.5,-0.94) 4(0.5,0.94) 5(0,0.94) 6(-0.5,0.94)
  rect 1.143x1.143 smd: 7(0,0)
DGN-16X60
  oval 0.406x1.524 smd: 1(-0.975,-2.311) 2(-0.325,-2.311) 3(0.325,-2.311) 4(0.975,-2.311) 5(0.975,2.311) 6(0.325,2.311) 7(-0.325,2.311) 8(-0.975,2.311)
  rect 2.032x2.032 smd: 9(0,0)
DRB8-14X33-PAD
  rect 0.356x0.851 smd: 1(-0.975,-1.473) 2(-0.325,-1.473) 3(0.325,-1.473) 4(0.975,-1.473) 5(0.975,1.473) 6(0.325,1.473) 7(-0.325,1.473) 8(-0.975,1.473)
  rect 2.388x1.6 smd: 9(0,0)
HEADER10X2
  rect 1.524x1.524 hole 0.965: 1(0,0)
  round 1.524 hole 0.965: 2(2.54,0) 3(0,-2.54) 4(2.54,-2.54) 5(0,-5.08) 6(2.54,-5.08) 7(0,-7.62) 8(2.54,-7.62) 9(0,-10.16) 10(2.54,-10.16)
HEADER10X2_SMD
  rect 0.711x2.87 smd: 1(-5.715,-2.705) 2(-5.715,2.705) 3(-4.445,-2.705) 4(-4.445,2.705) 5(-3.175,-2.705) 6(-3.175,2.705) 7(-1.905,-2.705) 8(-1.905,2.705) 9(-0.635,-2.705) 10(-0.635,2.705) 11(0.635,-2.705) 12(0.635,2.705) 13(1.905,-2.705) 14(1.905,2.705) 15(3.175,-2.705) 16(3.175,2.705) 17(4.445,-2.705) 18(4.445,2.705) 19(5.715,-2.705) 20(5.715,2.705)
HEADER23X2
  rect 1.524x1.524 hole 1.016: 1(0,0)
  round 1.524 hole 1.016: 2(0,2.54) 3(2.54,0) 4(2.54,2.54) 5(5.08,0) 6(5.08,2.54) 7(7.62,0) 8(7.62,2.54) 9(10.16,0) 10(10.16,2.54) 11(12.7,0) 12(12.7,2.54) 13(15.24,0) 14(15.24,2.54) 15(17.78,0) 16(17.78,2.54) 17(20.32,0) 18(20.32,2.54) 19(22.86,0) 20(22.86,2.54) 21(25.4,0) 22(25.4,2.54) 23(27.94,0) 24(27.94,2.54) 25(30.48,0) 26(30.48,2.54) 27(33.02,0) 28(33.02,2.54) 29(35.56,0) 30(35.56,2.54) 31(38.1,0) 32(38.1,2.54) 33(40.64,0) 34(40.64,2.54) 35(43.18,0) 36(43.18,2.54) 37(45.72,0) 38(45.72,2.54) 39(48.26,0) 40(48.26,2.54) 41(50.8,0) 42(50.8,2.54) 43(53.34,0) 44(53.34,2.54) 45(55.88,0) 46(55.88,2.54)
LED0805-1
  rect 1.143x1.27 smd: 1(-1.143,0) 2(1.143,0)
LQFP64_10X10
  rect 1.651x0.305 smd: 1(-5.6,3.75) 2(-5.6,3.25) 3(-5.6,2.75) 4(-5.6,2.25) 5(-5.6,1.75) 6(-5.6,1.25) 7(-5.6,0.75) 8(-5.6,0.25) 9(-5.6,-0.25) 10(-5.6,-0.75) 11(-5.6,-1.25) 12(-5.6,-1.75) 13(-5.6,-2.25) 14(-5.6,-2.75) 15(-5.6,-3.25) 16(-5.6,-3.75) 33(5.6,-3.75) 34(5.6,-3.25) 35(5.6,-2.75) 36(5.6,-2.25) 37(5.6,-1.75) 38(5.6,-1.25) 39(5.6,-0.75) 40(5.6,-0.25) 41(5.6,0.25) 42(5.6,0.75) 43(5.6,1.25) 44(5.6,1.75) 45(5.6,2.25) 46(5.6,2.75) 47(5.6,3.25) 48(5.6,3.75)
  rect 0.305x1.651 smd: 17(-3.75,-5.6) 18(-3.25,-5.6) 19(-2.75,-5.6) 20(-2.25,-5.6) 21(-1.75,-5.6) 22(-1.25,-5.6) 23(-0.75,-5.6) 24(-0.25,-5.6) 25(0.25,-5.6) 26(0.75,-5.6) 27(1.25,-5.6) 28(1.75,-5.6) 29(2.25,-5.6) 30(2.75,-5.6) 31(3.25,-5.6) 32(3.75,-5.6) 49(3.75,5.6) 50(3.25,5.6) 51(2.75,5.6) 52(2.25,5.6) 53(1.75,5.6) 54(1.25,5.6) 55(0.75,5.6) 56(0.25,5.6) 57(-0.25,5.6) 58(-0.75,5.6) 59(-1.25,5.6) 60(-1.75,5.6) 61(-2.25,5.6) 62(-2.75,5.6) 63(-3.25,5.6) 64(-3.75,5.6)
MC-306
  rect 1.3x1.9 smd: (2.75,1.6) (2.75,-1.6) 1(-2.75,-1.6) 2(-2.75,1.6)
MTGH200C125D_PL
  round 4.445 hole 3.175: 1(0,0)
QFN28_5X5
  rect 0.95x0.305 smd: 1(-2.4,1.5) 2(-2.4,1) 3(-2.4,0.5) 4(-2.4,0) 5(-2.4,-0.5) 6(-2.4,-1) 7(-2.4,-1.5) 15(2.4,-1.5) 16(2.4,-1) 17(2.4,-0.5) 18(2.4,0) 19(2.4,0.5) 20(2.4,1) 21(2.4,1.5)
  rect 0.305x0.95 smd: 8(-1.5,-2.4) 9(-1,-2.4) 10(-0.5,-2.4) 11(0,-2.4) 12(0.5,-2.4) 13(1,-2.4) 14(1.5,-2.4) 22(1.5,2.4) 23(1,2.4) 24(0.5,2.4) 25(0,2.4) 26(-0.5,2.4) 27(-1,2.4) 28(-1.5,2.4)
  rect 3.302x3.302 smd: 29(0,0)
QFN32_5X5MM_EP3P3MM
  oval 0.254x0.838 smd: 1(-1.751,-2.515) 8(1.751,-2.515) 17(1.751,2.515) 24(-1.751,2.515)
  rect 0.254x0.838 smd: 2(-1.251,-2.515) 3(-0.751,-2.515) 4(-0.25,-2.515) 5(0.25,-2.515) 6(0.751,-2.515) 7(1.251,-2.515) 18(1.251,2.515) 19(0.751,2.515) 20(0.25,2.515) 21(-0.25,2.515) 22(-0.751,2.515) 23(-1.251,2.515)
  oval 0.838x0.254 smd: 9(2.515,-1.751) 16(2.515,1.751) 25(-2.515,1.751) 32(-2.515,-1.751)
  rect 0.838x0.254 smd: 10(2.515,-1.251) 11(2.515,-0.751) 12(2.515,-0.25) 13(2.515,0.25) 14(2.515,0.751) 15(2.515,1.251) 26(-2.515,1.251) 27(-2.515,0.751) 28(-2.515,0.25) 29(-2.515,-0.25) 30(-2.515,-0.751) 31(-2.515,-1.251)
  rect 3.404x3.404 smd: 33(0,0)
RJ45-7499010211A
  round 1.016 hole 3.251 unplated: (-1.27,-6.35) (10.16,-6.35)
  rect 1.422x1.422 hole 0.965: 1(0,0)
  round 1.422 hole 0.965: 2(1.27,2.54) 3(2.54,0) 4(3.81,2.54) 5(5.08,0) 6(6.35,2.54) 7(7.62,0) 8(8.89,2.54)
  round 1.524 hole 1.016: 9(-1.88,-11.252) 10(0.66,-9.728) 11(8.23,-11.252) 12(10.77,-9.728)
  round 2.286 hole 1.6: 13(-3.429,-3.302) 14(12.319,-3.302)
SM-7351-IND-0805
  rect 1.397x1.549 smd: 1(-0.95,0) 2(0.95,0)
SM_CRY_SCC18
  rect 1.4x2.2 smd: 1(-1.25,3.2) 2(-1.25,-3.2) 3(1.25,-3.2) 4(1.25,3.2)
SMINI6-F3-B
  rect 0.305x0.95 smd: 1(0.65,0.75) 2(0,0.75) 3(-0.65,0.75) 4(-0.65,-0.75) 5(0,-0.75) 6(0.65,-0.75)
SOIC_8
  rect 0.61x2.184 smd: 1(-1.905,-2.603)
  oval 0.61x2.184 smd: 2(-0.635,-2.603) 3(0.635,-2.603) 4(1.905,-2.603) 5(1.905,2.603) 6(0.635,2.603) 7(-0.635,2.603) 8(-1.905,2.603)
SOT23-6
  rect 0.635x1.016 smd: 1(-0.953,-1.295) 2(0,-1.295) 3(0.953,-1.295) 4(0.953,1.295) 5(0,1.295) 6(-0.953,1.295)
SW3_4X2P5
  round 0.762 hole 0.762 unplated: (0,0)
  rect 0.787x1.702 smd: 1(-1.7,0) 2(1.7,0)
  rect 0.787x1.092 smd: 3(0,-1.65)
TP1-8040
  round 1.524 hole 1.016: 1(0,0)
TP60C_SMD
  round 1.27 smd: 1(0,0)
U_6_DRY
  rect 0.305x0.508 smd: 1(-0.5,-0.439) 2(0,-0.439) 3(0.5,-0.439) 4(0.5,0.439) 5(0,0.439) 6(-0.5,0.439)
U_8_DCU
  rect 0.254x1.27 smd: 1(-0.749,-1.473) 2(-0.249,-1.473) 3(0.249,-1.473) 4(0.749,-1.473) 5(0.749,1.473) 6(0.249,1.473) 7(-0.249,1.473) 8(-0.749,1.473)
U_48_RSL
  rect 0.8x0.2 smd: 1(-3.075,2.2) 2(-3.075,1.8) 3(-3.075,1.4) 4(-3.075,1) 5(-3.075,0.6) 6(-3.075,0.2) 7(-3.075,-0.2) 8(-3.075,-0.6) 9(-3.075,-1) 10(-3.075,-1.4) 11(-3.075,-1.8) 12(-3.075,-2.2) 25(3.075,-2.2) 26(3.075,-1.8) 27(3.075,-1.4) 28(3.075,-1) 29(3.075,-0.6) 30(3.075,-0.2) 31(3.075,0.2) 32(3.075,0.6) 33(3.075,1) 34(3.075,1.4) 35(3.075,1.8) 36(3.075,2.2)
  rect 0.2x0.8 smd: 13(-2.2,-3.075) 14(-1.8,-3.075) 15(-1.4,-3.075) 16(-1,-3.075) 17(-0.6,-3.075) 18(-0.2,-3.075) 19(0.2,-3.075) 20(0.6,-3.075) 21(1,-3.075) 22(1.4,-3.075) 23(1.8,-3.075) 24(2.2,-3.075) 37(2.2,3.075) 38(1.8,3.075) 39(1.4,3.075) 40(1,3.075) 41(0.6,3.075) 42(0.2,3.075) 43(-0.2,3.075) 44(-0.6,3.075) 45(-1,3.075) 46(-1.4,3.075) 47(-1.8,3.075) 48(-2.2,3.075)
  rect 4.05x4.05 smd: 49(-0.225,0.225)
unnamed
  round 1.016 smd: 1(0,0)
USB-MINI-SMT-NUM
  rect 0.508x2.261 smd: 1(-1.6,0) 2(-0.8,0) 3(0,0) 4(0.8,0) 5(1.6,0)
  rect 2.057x2.997 smd: 6(-4.928,0) 7(4.928,0)
  rect 2.057x3.988 smd: 8(-4.928,-4.242) 9(4.928,-4.242)
USB_A_SH
  round 1.651 hole 1.016: 1(0,0) 2(2.499,0) 3(4.501,0) 4(7,0)
  oval 2.032x3.429 hole 1.016x2.413: 5(-3.071,-2.71) 6(10.071,-2.71)
VLCF5020T
  custom 0.525x0.525 smd: 1(-1.7,0) 2(1.7,0)
XTAL2_5X3P2_SMD
  rect 1.778x2.54 smd: 1(-2.032,0) 2(2.032,0)
XTAL4_3P2X2P5_SMD
  rect 1.397x1.143 smd: 1(-1.1,-0.8) 2(1.1,-0.8) 3(1.1,0.8) 4(-1.1,0.8)
XTAL4_3P2X5SMD
  rect 1.6x1.27 smd: 1(-1.854,-1.105) 2(1.854,-1.105) 3(1.854,1.105) 4(-1.854,1.105)

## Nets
3V3EXP_FB: C166.1 R150.1(P1) R189.1(P1) U8.3(FB)
AGND: R15.1 U2.41(AGND)
DGND: C1.2 C2.2 C3.1 C4.1 C5.1 C6.2 C7.2 C8.1 C9.1 C10.1 C14.1 C15.1 C16.2 C17.1 C18.1 C19.1 C20.2 C21.2 C22.2 C25.2 C31.1 C32.1 C33.2 C34.2 C35.2 C36.2 C37.2 C38.2 C39.2 C40.2 C41.2 C42.2 C43.1 C44.1 C45.2 C46.2 C47.2 C48.2 C49.2 C50.1 C51.2 C52.1 C53.2 C54.2 C55.2 C56.2 C57.2 C58.1 C59.1 C60.2 C61.2 C62.1 C63.1 C64.1 C65.1 C66.1 C67.1 C68.1 C69.2 C70.1 C71.1 C72.2 C73.2 C74.2 C75.2 C76.2 C77.2 C78.2 C79.2 C80.2 C81.2 C82.2 C83.2 C84.2 C85.2 C86.2 C88.2 C89.1 C90.2 C91.2 C92.2 C93.2 C94.2 C95.2 C96.2 C97.2 C98.2 C99.2 C100.2 C101.2 C102.2 C103.2 C104.2 C105.2 C106.2 C107.2 C108.2 C109.2 C110.2 C111.2 C112.2 C113.2 C114.2 C115.2 C116.2 C117.2 C118.2 C119.2 C120.2 C121.2 C122.2 C123.2 C124.2 C125.2 C126.2 C127.2 C128.2 C129.2 C130.2 C131.2 C132.2 C133.2 C134.2 C135.1 C136.2 C137.1 C138.2 C139.2 C140.2 C141.2 C142.2 C143.2 C144.1 C145.2 C146.2 C147.2 C148.2 C149.1 C150.2 C151.2 C152.2 C153.1 C154.2 C155.1 C156.2 C157.1 C158.2 C159.2 C160.2 C161.2 C162.1 C163.1 C164.1 C165.1 D1.1(C) FB3.2 P2.4(P4) P3.5(G1) P4.6(VSS) P4.9(GND) P5.2 P7.8(GND#8) P7.10(GND#10) P7.12(GND#12) P7.16(GND#16) P7.20(GND#20) P8.1 P8.2(26) P9.1 P9.2(26) P9.43(22) P9.44(47) P9.45(23) P9.46(48) P10.8(GND) Q1.1(4) Q1.4 Q2.1(4) Q2.4 R1.1 R5.2 R9.1 R15.2 R16.1 R18.2 R20.2 R75.2 R76.1 R79.1 R100.2 R101.2 R102.2 R103.2 R104.2 R105.2 R106.2 R107.2 R108.2 R109.2 R110.2 R111.2 R112.2 R113.2 R114.2 R115.2 R116.2 R117.2 R118.2 R119.2 R125.2 R127.2 R128.1 R138.1 R145.2 R146.2 R147.2 R151.2 R157.2 R158.2 R159.2 R161.1 R167.1 R177.2 R186.2 R189.2(P2) R198.2 R212.2 R214.2 R216.2 R219.2 R220.2 S1.1(A1) TP1.1(TP) U1.2(GND) U1.6(E\N\) U2.30(PGND) U2.49(PPAD) U5.A1(VSS#A1) U5.A18(VSS#A18) U5.F8(VSS#F8) U5.G8(VSS#G8) U5.G9(VSS#G9) U5.G11(VSS#G11) U5.G12(VSS#G12) U5.H6(VSS#H6) U5.H7(VSS#H7) U5.H8(VSS#H8) U5.H9(VSS#H9) U5.H10(VSS#H10) U5.H12(VSS#H12) U5.J6(VSS#J6) U5.J7(VSS#J7) U5.J8(VSS#J8) U5.J9(VSS#J9) U5.J10(VSS#J10) U5.J11(VSS#J11) U5.K7(VSS#K7) U5.K9(VSS#K9) U5.K10(VSS#K10) U5.K11(VSS#K11) U5.L10(VSS#L10) U5.L11(VSS#L11) U5.L12(VSS#L12) U5.L13(VSS#L13) U5.M6(VSS#M6) U5.M7(VSS#M7) U5.M8(VSS#M8) U5.M9(VSS#M9) U5.M10(VSS#M10) U5.M12(VSS#M12) U5.M14(VSSA_USB#M14) U5.N7(VSS#N7) U5.N10(VSS#N10) U5.N11(VSS#N11) U5.N14(VSSA_USB#N14) U5.V1(VSS#V1) U5.V18(VSS#V18) U6.A3(VSS#A3) U6.A7(VSSQ#A7) U6.B2(VSSQ#B2) U6.B8(VSSQ#B8) U6.D2(VSSQ#D2) U6.D8(VSSQ#D8) U6.E3(VSS#E3) U6.E7(VSSQ#E7) U6.F2(VSSQ#F2) U6.F8(VSSQ#F8) U6.H2(VSSQ#H2) U6.H8(VSSQ#H8) U6.J3(VSS#J3) U6.J7(VSSDL) U6.N1(VSS#N1) U6.P9(VSS#P9) U7.1(A0) U7.2(A1) U7.3(A2) U7.4(VSS) U8.4(GND) U8.9(PAD) U9.1(GND) U9.9(PAD) U10.4(GND) U11.6(TEST) U11.29(VSS(FLAG)) U12.1(GND8) U12.5(GND7) U12.10(AGND) U12.11(GND6) U12.13(TEST) U12.15(GND5) U12.25(GND4) U12.32(ACBUS5) U12.35(GND3) U12.47(GND2) U12.51(GND1) U13.2(GND) U14.4(GND) U15.33(GND_EP) U16.2(GND) U17.4(GND)
GND_EARTH: MTG1.1(TP) MTG2.1(TP) MTG3.1(TP) MTG4.1(TP) P2.5(SHELD1) P2.6(PAD4) P3.6(G3) P3.7(G2) P3.8(G5) P3.9(G4) P4.10(CD) P4.12(GND2) P4.13(GND3) P4.14(GND4) P10.13(SHD1) P10.14(SHD2) R138.2 S1.3(A3)
GND_OSC0: C26.2 C27.2 U5.V11(VSS_OSC0)
GND_OSC1: C23.1 C24.1 U5.A5(VSS_RTC)
GNDA_ADC: C28.2 C29.2 C30.2 C87.2 FB3.1 P9.34(42) U5.A9(VREFN) U5.E8(VSSA_ADC)
VBUS_DET: R149.2 R151.1 U11.18(VBUS_DET)
VDD_1V8: C16.1 C72.1 C74.1 C75.1 C76.1 C77.1 C78.1 C79.1 C80.1 C82.1 C86.1 FB1.1 FB2.2 R12.2 R14.1 TP15.1(TP) U5.D10(VDDS_SRAM_MPU_BB) U5.E6(VDDS#E6) U5.E7(VDDS_PLL_DDR) U5.E9(VDDS_SRAM_CORE_BG) U5.E14(VDDS#E14) U5.F9(VDDS#F9) U5.K13(VDDS#K13) U5.N6(VDDS#N6) U5.N16(VDDA1P8V_USB0) U5.P9(VDDS#P9) U5.P14(VDDS#P14) U5.R16(VDDA1P8V_USB1)
VDD_1V8FT: C152.1 C162.2 C163.2 C164.2 U12.12(VCOREC) U12.37(VCOREB) U12.49(VREGOUT) U12.64(VCOREA)
VDD_3V3A: C42.1 C43.2 C51.1 C52.2 C56.1 C57.1 C58.2 C59.2 C60.1 C61.1 C62.2 C63.2 C64.2 C65.2 C66.2 C67.2 C68.2 C69.1 C70.2 C71.2 C81.1 C159.1 C160.1 C165.2 P4.4(VDD) R4.1 R7.1 R19.2 R23.1 R80.1 R81.1 R82.1 R83.1 R84.1 R85.1 R86.1 R87.1 R88.1 R89.1 R90.1 R91.1 R92.1 R93.1 R94.1 R95.1 R190.1 R191.1 R192.1 R193.1 R194.1 R195.1 U2.18(VIO) U5.E10(VDDSHV6#E10) U5.E11(VDDSHV6#E11) U5.E12(VDDSHV6#E12) U5.E13(VDDSHV6#E13) U5.F14(VDDSHV6#F14) U5.G14(VDDSHV6#G14) U5.H14(VDDSHV4#H14) U5.J14(VDDSHV4#J14) U5.K14(VDDSHV5#K14) U5.L14(VDDSHV5#L14) U5.N5(VDDSHV6#N5) U5.N15(VDDA3P3V_USB0) U5.P5(VDDSHV6#P5) U5.P6(VDDSHV6#P6) U5.P7(VDDSHV1#P7) U5.P8(VDDSHV1#P8) U5.P10(VDDSHV2#P10) U5.P11(VDDSHV2#P11) U5.P12(VDDSHV3#P12) U5.P13(VDDSHV3#P13) U5.R15(VDDA3P3V_USB1) U8.5(EN)
VDD_3V3B: C102.1 C122.1 C123.1 C135.2 C138.1 C139.1 C140.1 C141.1 C142.1 C143.1 C147.1 C148.1 C149.2 C150.1 C151.1 C154.1 C157.2 FB5.1 FB6.1 FB7.1 FB8.1 P7.5(TVDD) R121.2 R122.2 R123.2 R124.2 R126.1 R131.1 R148.1 R154.1 R155.1 R156.1 R162.1 R173.1 R174.1 R175.1 R176.1 R179.1 R181.1 R187.1 R196.2 R203.1 R210.1 R211.2 R213.2 R215.2 U7.8(VCC) U11.4(VDD33#4) U11.10(VDDCRREF/VDD33) U11.14(VDD33#14) U11.20(VDD33#20) U11.27(VDDPLLREF/VDD33) U12.20(VCCIOA) U12.28(ACBUS2) U12.31(VCCIOB#31) U12.42(VCCIOB#42) U12.56(VCCIOD) U13.6(VCC) U14.8(VCC) U15.12(VDDIO) U16.5(VCC)
VDD_3V3EXP: C166.2 P9.3(2) P9.4(27) R150.2(P2) U8.1(OUT)
VDD_5V: P5.1 P9.5(3) P9.6(28) U1.1(IN1) U1.7(IN0)
VDD_ADC: C87.1 FB2.1 P9.32(41) R78.1 U5.D8(VDDA_ADC)
VDD_CORE: C14.2 C31.2 C32.2 C33.1 C34.1 C35.1 C36.1 C37.1 C38.1 C39.1 C40.1 C41.1 C48.1 C49.1 C50.2 C53.1 C54.1 C55.1 R13.2 TP17.1(TP) U5.F6(VDD_CORE1) U5.F7(VDD_CORE2) U5.G6(VDD_CORE3) U5.G7(VDD_CORE4) U5.G10(VDD_CORE5) U5.H11(VDD_CORE6) U5.J12(VDD_CORE7) U5.K6(VDD_CORE8) U5.K8(VDD_CORE9) U5.K12(VDD_CORE10) U5.L6(VDD_CORE11) U5.L7(VDD_CORE12) U5.L8(VDD_CORE13) U5.L9(VDD_CORE14) U5.M11(VDD_CORE15) U5.M13(VDD_CORE16) U5.N8(VDD_CORE17) U5.N9(VDD_CORE18) U5.N12(VDD_CORE19) U5.N13(VDD_CORE20)
VDD_FTREGIN: FB8.2 U12.50(VREGIN)
VDD_FTVPHY: C158.1 FB7.2 U12.4(VPHY)
VDD_FTVPLL: C161.1 FB6.2 U12.9(VPLL)
VDD_LED: C100.1 FB4.1 R96.1 R97.1 R98.1 R99.1
VDD_MPU: C15.2 C44.2 C45.1 C46.1 C47.1 R204.2 U5.F10(VDD_MPU1) U5.F11(VDD_MPU2) U5.F12(VDD_MPU3) U5.F13(VDD_MPU4) U5.G13(VDD_MPU5) U5.H13(VDD_MPU6) U5.J13(VDD_MPU7)
VDD_MPUON: TP5.1(TP) U5.A2(VDD_MPU_MON)
VDD_PHYA: C119.1 C120.1 C121.1 FB5.2 R129.2 R130.2 R133.2 R134.2 R142.2 U15.1(VDD2A) U15.27(VDD1A)
VDD_PLL: C73.1 C88.1 C99.1 FB1.2 U5.H15(VDDS_PLL_MPU) U5.R10(VDDS_PLL_CORE_LCD) U5.R11(VDDS_OSC)
VDD_RTC: C97.1 U5.D6(CAP_VDD_RTC)
VDDS_DDR: C89.2 C90.1 C91.1 C92.1 C93.1 C94.1 C95.1 C96.1 C103.1 C104.1 C105.1 C106.1 C107.1 C108.1 C109.1 C110.1 C111.1 C112.1 C113.1 C114.1 C115.1 C116.1 C117.1 R14.2 R74.1 TP18.1(TP) U5.E5(VDDS_DDR#E5) U5.F5(VDDS_DDR#F5) U5.G5(VDDS_DDR#G5) U5.H5(VDDS_DDR#H5) U5.J5(VDDS_DDR#J5) U5.K5(VDDS_DDR#K5) U5.L5(VDDS_DDR#L5) U6.A1(VDD#A1) U6.A9(VDDQ#A9) U6.C1(VDDQ#C1) U6.C3(VDDQ#C3) U6.C7(VDDQ#C7) U6.C9(VDDQ#C9) U6.E1(VDD#E1) U6.E9(VDDQ#E9) U6.G1(VDDQ#G1) U6.G3(VDDQ#G3) U6.G7(VDDQ#G7) U6.G9(VDDQ#G9) U6.J1(VDDL) U6.J9(VDD#J9) U6.M9(VDD#M9) U6.R1(VDD#R1)
AIN0: P9.39(20) U5.B6(AIN0)
AIN1: P9.40(45) U5.C7(AIN1)
AIN2: P9.37(19) U5.B7(AIN2)
AIN3: P9.38(44) U5.A7(AIN3)
AIN4: P9.33(17) U5.C8(AIN4)
AIN5: P9.36(43) U5.B8(AIN5)
AIN6: P9.35(18) U5.A8(AIN6)
AIN7: R8.1 R9.2 U5.C9(AIN7)
BAT: C3.2 P6.1 P6.2 U2.4(BAT1) U2.5(BAT2)
BAT_SENSE: P6.3 U2.6(BAT_SENSE)
BAT_TEMP: P6.4 U2.11(TS)
BL_IN: P6.8 U2.37(L4)
BL_ISET1: P6.6 U2.35(ISET1)
BL_ISET2: P6.5 U2.36(ISET2)
BL_OUT: C7.1 P6.7 U2.38(FB_WLED)
BL_SINK1: P6.9 U2.34(ISINK1)
BL_SINK2: P6.10 U2.33(ISINK2)
CAP_VBB_MPU: C85.1 U5.C10(CAP_VBB_MPU)
CAP_VDD_SRAM_CORE: C83.1 U5.D9(CAP_VDD_SRAM_CORE)
CAP_VDD_SRAM_MPU: C84.1 U5.D11(CAP_VDD_SRAM_MPU)
CD/EMU4: R185.1 R197.2 U5.C15(SPI0_CS1/UART3_RXD/ECAP1_IN_PWM)
CLKOUT2: P9.41(21) R184.2 R218.2
CLKOUT_SRC: R218.1 R221.1 U5.D14(EVENT_INTR1/TCLKIN/CLKOUT2/TIME)
COL/CRS_DV/MODE2: R207.2 U15.15(COL/CRS_DV/MODE2)
CRFILT: C146.1 U11.9(CRFILT)
CRS_DV/MODE2: R122.1 R127.1 R139.2 U15.14(CRS)
DC_IN: C1.1 U1.4(OUT0) U1.5(OUT1) U2.10(AC)
DDR_A0: R29.1 U6.M8(A0)
DDR_A1: R25.1 U6.M3(A1)
DDR_A2: R30.1 U6.M7(A2)
DDR_A3: R26.1 U6.N2(A3)
DDR_A4: R31.1 U6.N8(A4)
DDR_A5: R32.1 U6.N3(A5)
DDR_A6: R33.1 U6.N7(A6)
DDR_A7: R34.1 U6.P2(A7)
DDR_A8: R35.1 U6.P8(A8)
DDR_A9: R36.1 U6.P3(A9)
DDR_A10: R37.1 U6.M2(A10)
DDR_A11: R38.1 U6.P7(A11)
DDR_A12: R39.1 U6.R2(A12)
DDR_A13: R40.1 R120.1(P1)
DDR_A13R: R120.2(P2) U6.R8((RFU)A13)
DDR_BA0: R41.1 U6.L2(BA0)
DDR_BA1: R42.1 U6.L3(BA1)
DDR_BA2: R43.1 U6.L1(BA2)
DDR_CASN: R64.1 U6.L7(CASN)
DDR_CKE: R62.1 U6.K2(CKE)
DDR_CLK: R60.1 U6.J8(CK)
DDR_CLKN: R61.1 U6.K8(CKN)
DDR_CSN: R63.1 U6.L8(CSN)
DDR_D0: R44.1 U6.G8(DQ0)
DDR_D1: R45.1 U6.G2(DQ1)
DDR_D2: R46.1 U6.H7(DQ2)
DDR_D3: R47.1 U6.H3(DQ3)
DDR_D4: R48.1 U6.H1(DQ4)
DDR_D5: R49.1 U6.H9(DQ5)
DDR_D6: R50.1 U6.F1(DQ6)
DDR_D7: R51.1 U6.F9(DQ7)
DDR_D8: R52.1 U6.C8(DQ8)
DDR_D9: R53.1 U6.C2(DQ9)
DDR_D10: R54.1 U6.D7(DQ10)
DDR_D11: R55.1 U6.D3(DQ11)
DDR_D12: R56.1 U6.D1(DQ12)
DDR_D13: R57.1 U6.D9(DQ13)
DDR_D14: R58.1 U6.B1(DQ14)
DDR_D15: R59.1 U6.B9(DQ15)
DDR_DQM0: R67.1 U6.F3(LDM)
DDR_DQM1: R70.1 U6.B3(UDM)
DDR_DQS0: R68.1 U6.F7(LDQS)
DDR_DQS1: R71.1 U6.B7(UDQS)
DDR_DQSN0: R69.1 U6.E8(LDQSN)
DDR_DQSN1: R72.1 U6.A8(UDQSN)
DDR_ODT: R73.1 U6.K9(ODT)
DDR_RASN: R65.1 U6.K7(RASN)
DDR_RESETN: TP3.1(TP) U5.G2(DDR_RESETN)
DDR_VREF: C118.1 R74.2 R75.1 U5.J4(VREFSSTL) U6.J2(VREF)
DDR_VTP: R76.2 U5.J3(DDR_VTP)
DDR_WEN: R66.1 U6.K3(WEN)
EHRPWM1A: P9.14(32) U5.U14(GPMC_A2/GMII2_TXD3/RGMII2_TD3/M)
EHRPWM1B: P9.16(33) U5.T14(GPMC_A3/GMII2_TXD2/RGMII2_TD2/M)
EHRPWM2A: P8.19(10) U5.U10(GPMC_AD8/LCD_DATA23/MMC1_DAT0/M)
EHRPWM2B: P8.13(7) U5.T10(GPMC_AD9/LCD_DATA22/MMC1_DAT1/M)
EMU2R: P7.17(EMU2) R183.2
EMU3R: P7.18(EMU3) R184.1
EMU4R: P7.19(EMU4) R185.2
EMU_RSTN: C156.1 P7.15(SRST) R182.2
ENZ_KALDO_1P8V: R79.2 U5.B4(ENZ_KALDO_1P8V)
F_ADBUS0: R164.1 U12.16(ADBUS0)
F_ADBUS1: R165.1 U12.17(ADBUS1)
F_ADBUS2: R166.1 U12.18(ADBUS2)
F_ADBUS3: R168.1 U12.19(ADBUS3)
F_ADBUS4: R169.1 U12.21(ADBUS4)
F_ADBUS6: R170.1 U12.23(ADBUS6)
F_ADBUS7: R171.1 U12.30(ACBUS4)
F_EECS: R173.2 U12.63(EECS) U13.5(CS)
F_EEDATA: R188.2 U12.61(EEDATA) U13.3(DIN)
F_EEDOUT: R187.2 R188.1 U13.1(DOUT)
F_EESK: R174.2 U12.62(EECLK) U13.4(SK)
FT_DM: U11.28(USBDM_DN1) U12.7(USBDM)
FT_DP: U11.1(USBDP_DN1) U12.8(USBDP)
FT_REF: R167.2 U12.6(REF)
FT_RESETN: R175.2 U12.14(R\E\S\E\T\)
FT_SRESET: R162.2 U12.26(ACBUS0) U14.5(2A)
FT_SRESETB: R163.1 U16.6(1Y)
FT_SRESETN: R172.1 U14.3(2Y)
FT_VBUS: R181.2 U11.7(PRTPWR1) U12.59(BCBUS7) U14.6(2B)
GPIO0_7: P9.42(46) R202.1 R217.1
GPIO0_7SRC: R217.2 U5.C18(ECAP0_IN_PWM0_OUT/UART3_TXD/SPI)
GPIO0_26: P8.14(32) U5.T11(GPMC_AD10/LCD_DATA21/MMC1_DAT2/)
GPIO0_27: P8.17(9) U5.U12(GPMC_AD11/LCD_DATA20/MMC1_DAT3/)
GPIO1_0: P8.25(13) U5.U7(GPMC_AD0/MMC1_DAT0//////GPIO1_0)
GPIO1_1: P8.24(37) U5.V7(GPMC_AD1/MMC1_DAT1//////GPIO1_1)
GPIO1_2: P8.5(3) U5.R8(GPMC_AD2/MMC1_DAT2//////GPIO1_2)
GPIO1_3: P8.6(28) U5.T8(GPMC_AD3/MMC1_DAT3//////GPIO1_3)
GPIO1_4: P8.23(12) U5.U8(GPMC_AD4/MMC1_DAT4//////GPIO1_4)
GPIO1_5: P8.22(36) U5.V8(GPMC_AD5/MMC1_DAT5//////GPIO1_5)
GPIO1_6: P8.3(2) U5.R9(GPMC_AD6/MMC1_DAT6//////GPIO1_6)
GPIO1_7: P8.4(27) U5.T9(GPMC_AD7/MMC1_DAT7//////GPIO1_7)
GPIO1_12: P8.12(31) U5.T12(GPMC_AD12/LCD_DATA19/MMC1_DAT4/)
GPIO1_13: P8.11(6) U5.R12(GPMC_AD13/LCD_DATA18/MMC1_DAT5/)
GPIO1_14: P8.16(33) U5.V13(GPMC_AD14/LCD_DATA17/MMC1_DAT6/)
GPIO1_15: P8.15(8) U5.U13(GPMC_AD15/LCD_DATA16/MMC1_DAT7/)
